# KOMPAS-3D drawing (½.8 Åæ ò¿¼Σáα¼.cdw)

Views: Вид 1, Вид 2
Referenced files in C:\Program Files\ASCON\KOMPAS-3D V10\Sys\: SPDS.lcs, Graphic.lcs
Referenced files in \\F-server\проектирование\Проекты\РЗА и ПА Тюменские РС\4. Проект\ЭП\Туринская\Рабочая документация\: план располодения оборудования на ПС.cdw
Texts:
  Текст на чертеже
  Размерные надписи
  Шероховатость
  Линия-выноска #1
  Линия-выноска #2
  Линия-выноска #3
  Отклонения формы и база
  Заголовок таблицы
  Ячейка таблицы
  Стрелка вида
  Обозначение изменения
  Фигурная скобка
  Номер узла
  Марка координационной оси
  VRCB
  Выносная надпись
  Обозначение узла
  Марка/позиционное обозначение с линией-выноской
  Марка/позиционное обозначение на линии
  Марка/позиционное обозначение без линии-выноски
  Лит-Масса-Масштаб
  Материал-Предприятие
  Title Specification
  Body Specification ( left align )
  Body Specificaton ( centered )
  Без имени
  Normal
  heading 1
  Знак Знак Знак Знак Знак Знак
  Verdana
  Body Text
  MS Sans Serif
  Txt
  Simplex
  TXT
  Обычный
  Термин
  Список определений
  Адрес
  Цитаты
  Форматированный
  Courier New
  Z-конец формы
  Z-начало формы
  Additional DXF text style 0
  Абзац Знак
  Body Text 3
  Title
  ТекстШаг1
  Шрифт 2.5
  Заголовки
  txt
  heading 2
  AGOpus
  footer
  Денис
  RUSTXT
  Обычный (веб)
  ООббыыччнныыйй
  Definition Term
  Definition List
  Address
  Blockquote
  Preformatted
  z-Bottom of Form
  z-Top of Form
  header
  NormalParagraphStyle
  ссылки
  Подпись в квадратике
  табл
  цепи
  Маркировка
  клеммы, контакты
  тексты табл
  Тексты. 3,2
  ЗОНА_привяз
  текст переноса
  ТТееррммиинн
  ССппииссоокк ооппррееддееллеенниийй
  ААддрреесс
  ЦЦииттааттыы
  ФФооррммааттиирроовваанннныыйй
  Z-ккооннеецц ффооррммыы
  Z-ннааччааллоо ффооррммыы
  GOST 2.304 type A
  rustxt
  heading 8
  heading 3
  heading 6
  heading 7
  russ
  heading 4
  heading 5
  heading 9
  HeliosLight
  Pa3
  Pa1
  Три с половиной
  style2
  Table Contents
  Table Heading
  ГОСТ_МНЕ
  ESK - Обозначение
  маркировка
  ISOCP
  ROMANS
  SIMPLEX
  Текст 3,5
  Tahoma
  CNBNDG+TimesNewRoman
  Subtitle
  FR5
  romanc
  eskd1
  Pa15
  Pa18
  Аппараты
  подписи
  Состав чартежа
  ячейка табл.
  Ссылки
  Пояснения
  Клеммник текст
  CM12
  romans
  gif
  Пояснения 2
  текст табл
  ISOCPEUR
  CC С?т?и?л?ь? П?о? ц?е?н?т?р?у?
  Normal (Web)
  ошиновка
  лотки
  съемка
  Молниеотвод
  Экспликация зданий и сооружений
  Номер
  на плане
  Постоянные здания и сооружения
  ОПУ 8 №1
  Существующее
  ОПУ 8 №2
  КРУН 10 кВ
  Трансформатор 1Т, маслоприемник
  Существующий
  Трансформатор 2Т, маслоприемник
  Временные здания и сооружения
  III
  Вагон-дом для кратковременного отдых рабочих
  Уборная
  Дизельная электростанция
  Контейнеры для ТБО (0,75м 3 ) и жидких хоз.-быт.стоков(1м 3 )
  «Екатерина» 9,0х3,0
  Туалетная кабина "Люкс"
  ОАО ПКТИпромстрой
  АДС 45-Т400 РЯ
  Примечания:
  1. Для нужд строительства (размещение задействованного в строительстве персонала, обеспечение
  электроэнергией) использовать временные мобильные инвентарные здания;
  2. При выполнении всех строительно-монтажных работ на площадке необходимо руководствоваться
  требованиями СНиП 12-03-2001 "Безопасность труда в строительстве. Общие требования",
  СНиП 12-04-2002 "Безопасность труда в строительстве. Строительное производство", а также
  ПОТ-РМ-016-2001/РД 153-34.0-03.150-00 "Межотраслевые правила по охране труда (правила
  безопасности) при эксплуатации электроустановок";
  3. Наружное освещение строительной площадки осуществляется за счет существующего освещения;
  4. Под временные сооружения (поз. II, III и IV) устраивается площадка из дорожных плит ПД 60-20 на
  щебеночном основании толщиной 15см;
  5. На период строительства для электроснабжения временных зданий и сооружений использовать ди-
  зельную электростанцию. Прокладку  кабеля от дизельной электростанции до вагончиков выполнить
  в воздушном исполнении в гофрированной трубе диаметром 30 мм, на вагончиках кабель закрепить
  скобами. Щиток временного электроснабжения навесить на стенку вагона-дома для отдыха рабочих;
  6. При выполнении монтажных работ использовать инвентарные лестницы и леса;
  7. На паспорте-стенде строительного объекта  должен быть план пожарной защиты с нанесенными
  строящимися и вспомогательными зданиями и сооружениями, въездами, подъездами, местонахождениями
  водоисточников, средств пожаротушения и связи (согласно ППБ-01-03 п.575);
  8. Тонкой линией изображено существующее оборудование, замена которого проектом не предусматри-
  вается, утолщенной - вновь устанавливаемое оборудование.
  9. Грузовысотные характеристики КМУ ИНМАН ИМ-150 см. 16/01-ПОС,л.7.
  - предупреждающий знак
  "Опасно. Возможно падение груза"
  "Опасность поражения электрическим током"
  - стоянка крана во время производства работ
  - стенд с противопожарным инвентарем
  - знак ограничения поворота стрелы
  - опасная зона работы при перемещении грузов
  - пути перемещения
  строительной техники
  Условные обозначения:
  - паспорт-стенд строительного
  объекта
  - запрещающий знак ограничения
  скорости движения автомобиля
  в.заг.40,98
  в.заг.40,85
  шк.
  в.кр.п.38,95
  в.заг.40,81
  в.заг.40,96
  в.кр.п.38,94
  ср.п.49,43
  каб.лот.
  каб.лоток
  ОПУ 2
  в.зд.38,44
  в.зд.38,15
  КРУН-10 кВ
  ОПУ 1
  в.зд.38,46
  ж/б пл.
  каб.эстакада 10 кВ
  об-35,00
  об-34,60
  РП 2
  РП 1
  кабели 10 кВ по забору
  КМУ ИНМАН ИМ-150
  Слой 1
  ВЛ 110 кВ
  K5LT_BASIC_RGB_0_0_255_THICK_0.6
  K5LT_AXLED_RGB_255_128_0_SC_1_THICK_0.09
  K5LT_DASHED_RGB_0_0_0_SC_1_THICK_0.09
  K5LT_AXLED_RGB_255_128_0_SC_1_THICK_0.18
  POLYLINE_STYLE_0.18_RGB_0_0_0
  POLYLINE_STYLE_0.20_RGB_0_0_0
  POLYLINE_STYLE_0.18_RGB_0_80_80
  Стили документа
  Бортовой автомобиль КамАЗ 43114-027-02
  АТ ППР#010#0104
  ГИП
  Н.контр.
  Гл.спец.
  Разраб.
  Перезавод ВЛ на ПС Тюмень. Реконструкция устройств
  РЗ и ПА на обратных концах отходящих ВЛ,
  ВОЛС Тюменского ТПО
  ПС 110/10 кВ Химфарм
  Матвеев
  Ромин
  Шашерин
  Строительный генеральный план
  Королева
  Общие технические условия на средний ремонт
Dimensions and other numbers on the sheet: 16/01-ПОС; 7; 2,5; 1,8; 2.5; 3,2_; 3.5; 3,2; 2,5 (контакты, клеммы); 3,2 (надписи); 3,2 (Зоны); 5; 2,5_01; 2,5_3; 3,5_01; 3,5_tabl; 5_заголовок; 2,3_; 3,2_зона не привяз; 3,5; 3.2 маркировка; 3,2 элементы; 3,2 линия; 3,2 таблица; 2,5 грязносинь; 2.5 курсив; 2.5_Э5_надписи; 2.5_Э5_ссылки; 2.5_кабель; 3.2; 2.5 надписи; 3 и 5; 5,0_белый_подчёркнутый; 3.2 фиол; 3.2 (текст); 1; 2; 3; 4; 9,6; 34,78; 34,40; 34,47; 34,37; 34,52; 34,80; 34,65; 35,01; 34,73; 34,62; 34,60; 34,49; 34,56; 34,93; 34,88; 34,81; 34,76; 34,79; 34,74; 34,32; 34,66; 35,83; 34,38; 35,92; 34,42; 35,37; 35,15; 35,32; 34,77; 34,58; 34,46; 34,59; 35,00; 34,83; 34,87; 34,53; 34,28; 34,68; 34,67; 34,48; 34,82; 35,07; 34,54; 3 пр.; 7 пр.; 110 кВ; 1065; 1780; 1800; 1500; 16; 20; 19; 18; 17; 05.13; 8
